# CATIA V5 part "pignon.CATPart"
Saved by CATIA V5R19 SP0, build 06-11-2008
Part number: pignon
Bounding box of the stored display mesh (mm): x -10 to 10, y -10 to 10, z -5 to 5
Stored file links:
  C:\Documents and Settings\alenoir\Bureau\mécanisme\pignon.CATPart
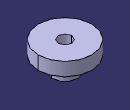
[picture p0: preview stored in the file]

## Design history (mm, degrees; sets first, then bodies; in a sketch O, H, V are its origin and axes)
Body1 (main body)
  Sketch1 on xy-plane, origin (0, 0, 0), H (1, 0, 0), V (0, 1, 0)
    circle A1 centre (0, 0) radius 10
    radius A1 = 10
  Pad1: profile Sketch1, direction (0, 0, 1), length 5
  Sketch2 on start face of Pad1, origin (0, 0, 0), H (1, 0, 0), V (0, 1, 0)
    circle A1 centre (0, 0) radius 5
    radius A1 = 5
  Pad2: profile Sketch2, direction (0, 0, -1), length 5
  Sketch3 on end face of Pad2, origin (0, 0, -5), H (1, 0, 0), V (0, 1, 0)
    circle A1 centre (0, 0) radius 2.5
    radius A1 = 2.5
  Pocket1: profile Sketch3, direction (0, 0, 1), through (limit type 6)
  Sketch4 on end face of Pad2, origin (0, 0, -5), H (1, 0, 0), V (0, 1, 0)
    circle A1 centre (0, 0) radius 5
    reference projected circle E1 centre (0, 0) radius 5 from edge [end face of Pad2 | face of Pad2 from Sketch2.A1]
    reference projected circle E2 centre (0, 0) radius 5 from edge [end face of Pad2 | face of Pad2 from Sketch2.A1]
    concentricity: A1 E1
    coincidence: A1 E2
  Sketch5 on end face of Pad1, origin (0, 0, 5), H (1, 0, 0), V (0, 1, 0)
    circle A1 centre (0, 0) radius 10
    reference projected circle E1 centre (0, 0) radius 10 from edge [face of Pad1 from Sketch1.A1 | end face of Pad1]
    reference projected circle E2 centre (0, 0) radius 10 from edge [face of Pad1 from Sketch1.A1 | end face of Pad1]
    concentricity: A1 E1
    coincidence: A1 E2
